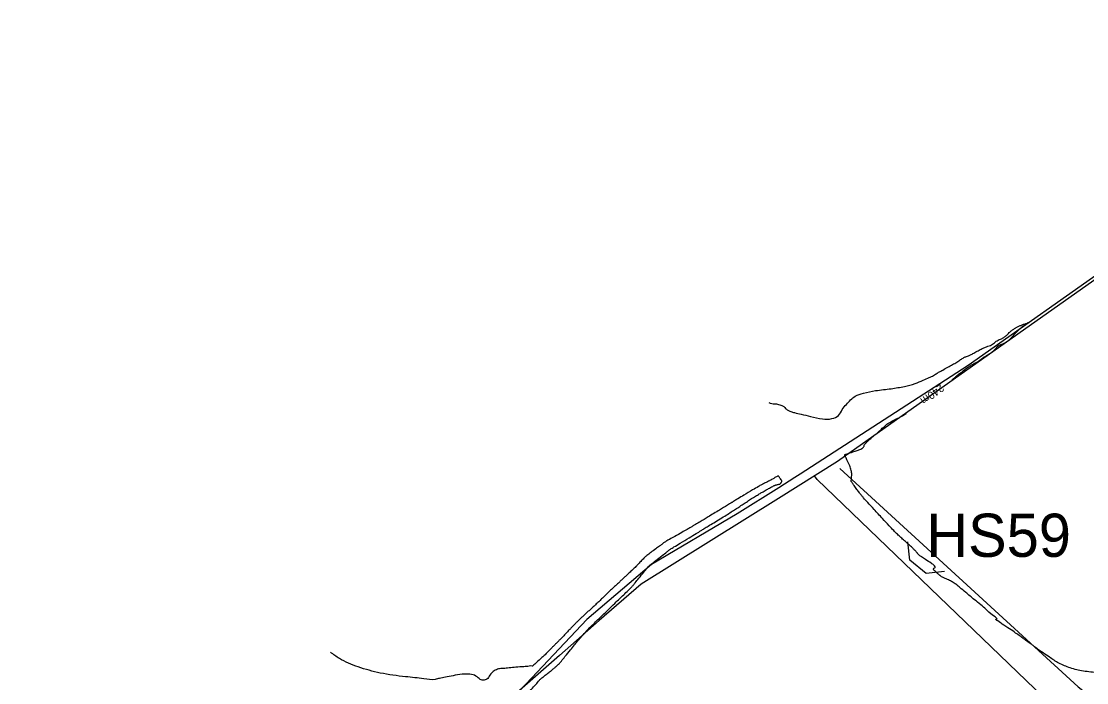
# Model space of a CAD drawing. Extents: x -478495 to -472450, y -1118050 to -1113745.
# Drawn here: x -477223 to -476976.4, y -1115068.9 to -1114915.9 of the extents above; entities that cross this region are included whole.
import ezdxf

# ---------------------------------------------------------------- set-up
doc = ezdxf.new("R2010")
doc.units = 0
for name, color, linetype in [('cyklostezka', 7, 'Continuous'), ('hospodářské sjezdy', 7, 'Continuous'), ('hranice kú', 7, 'Continuous'), ('ObPÚ', 7, 'Continuous'), ('silnice', 7, 'Continuous'), ('vodní plochy', 7, 'Continuous'), ('Vrstevnice_hlavni', 7, 'Continuous'), ('Vrstevnice_popis', 7, 'Continuous'), ('Vrstevnice_vedlejsi', 7, 'Continuous')]:
    doc.layers.add(name, color=color, linetype=linetype)

msp = doc.modelspace()

# ---------------------------------------------------------------- linework, layer by layer
at = {"layer": 'cyklostezka'}
msp.add_lwpolyline([(-477033.5754190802, -1115019.3150603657), (-476978.4562666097, -1115069.8432601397), (-476859.56050309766, -1115163.970078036), (-476838.56618741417, -1115180.4272610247), (-476823.49769734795, -1115192.2844335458), (-476742.0352354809, -1115258.9995421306), (-476654.0177406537, -1115335.224940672), (-476615.8651919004, -1115370.6739552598), (-476567.0504242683, -1115426.523456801)], dxfattribs=at)
at = {"layer": 'hospodářské sjezdy'}
for p, q in [((-477017.369, -1115040.5760000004), (-477017.839838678, -1115036.3366136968)), ((-477013.55639166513, -1115043.6302121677), (-477017.369, -1115040.5760000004)), ((-477009.31643236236, -1115043.1645616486), (-477013.55639166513, -1115043.6302121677))]:
    msp.add_line(p, q, dxfattribs=at)
at = {"layer": 'hranice kú'}
for p, q in [((-476889.77970592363, -1114915.8720498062), (-477034.1014911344, -1115017.6843978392)), ((-477034.1014911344, -1115017.6843978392), (-477047.776208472, -1115026.2470712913)), ((-477047.776208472, -1115026.2470712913), (-477079.5238625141, -1115046.1264434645)), ((-477079.5238625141, -1115046.1264434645), (-477089.23482985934, -1115054.5264088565)), ((-477089.23482985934, -1115054.5264088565), (-477098.4353740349, -1115062.5768850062)), ((-477098.4353740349, -1115062.5768850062), (-477120.9851096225, -1115082.3079036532))]:
    msp.add_line(p, q, dxfattribs=at)
at = {"layer": 'ObPÚ'}
for p, q in [((-476889.77970592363, -1114915.8720498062), (-477034.1014911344, -1115017.6843978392)), ((-477034.1014911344, -1115017.6843978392), (-477047.776208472, -1115026.2470712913)), ((-477047.776208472, -1115026.2470712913), (-477079.5238625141, -1115046.1264434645)), ((-477079.5238625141, -1115046.1264434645), (-477089.23482985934, -1115054.5264088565)), ((-477089.23482985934, -1115054.5264088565), (-477098.4353740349, -1115062.5768850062)), ((-477098.4353740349, -1115062.5768850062), (-477120.9851096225, -1115082.3079036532))]:
    msp.add_line(p, q, dxfattribs=at)
at = {"layer": 'silnice'}
msp.add_lwpolyline([(-476200.5430969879, -1116268.1533225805), (-476239.9646638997, -1116179.1988064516), (-476260.9335824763, -1116109.5457419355), (-476288.6125549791, -1116007.1641290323), (-476289.4513117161, -1115970.2396129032), (-476274.35369035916, -1115930.797516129), (-476257.5785554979, -1115904.782516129), (-476369.13277385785, -1115816.6670000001), (-476386.7466654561, -1115803.239903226), (-476421.13569191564, -1115718.4813548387), (-476492.4300150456, -1115557.3561935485), (-476531.85169606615, -1115480.150387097), (-476576.30580343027, -1115421.4068387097), (-476632.5025051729, -1115358.4673225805), (-476738.18585476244, -1115266.156032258), (-476821.72644138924, -1115198.097580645), (-476986.4582147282, -1115072.218548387), (-477038.7966192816, -1115021.8669354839), (-477039.4315830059, -1115021.0219319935)], dxfattribs=at)
at = {"layer": 'vodní plochy'}
msp.add_lwpolyline([(-476969.074, -1114970.997), (-477003.853, -1114995.482), (-477042.717, -1115020.6670000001), (-477043.996, -1115021.391), (-477047.718, -1115023.7920000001), (-477057.356, -1115029.838), (-477077.169, -1115041.531), (-477092.092, -1115054.27), (-477110.00200000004, -1115073.251), (-477118.905, -1115081.598), (-477126.545, -1115085.486), (-477135.50800000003, -1115088.514), (-477142.313, -1115089.0590000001), (-477143.75, -1115088.538), (-477177.386, -1115076.347), (-477192.107, -1115077.213), (-477204.809, -1115080.97), (-477217.213, -1115089.231), (-477222.967, -1115093.062)], dxfattribs=at)
at = {"layer": 'Vrstevnice_hlavni'}
for points in [[(-477049.97945449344, -1115004.0292969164), (-477049.673, -1115004.193), (-477048.26, -1115004.404), (-477047.204, -1115004.683), (-477046.505, -1115005.027), (-477046.164, -1115005.438), (-477045.639, -1115005.805), (-477044.929, -1115006.127), (-477044.034, -1115006.405), (-477042.50800000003, -1115006.787), (-477040.351, -1115007.273), (-477037.56200000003, -1115007.8630000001), (-477035.407, -1115007.799), (-477033.886, -1115007.079), (-477033, -1115005.704), (-477032.06200000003, -1115004.503), (-477031.07300000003, -1115003.477), (-477030.034, -1115002.625), (-477028.119, -1115001.9070000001), (-477025.32800000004, -1115001.324), (-477021.663, -1115000.876), (-477018.599, -1115000.325), (-477016.13800000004, -1114999.672), (-477014.278, -1114998.9170000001), (-477012.873, -1114998.304), (-477011.923, -1114997.835), (-477011.428, -1114997.509), (-477010.705, -1114997.08), (-477009.754, -1114996.549), (-477008.574, -1114995.914), (-477007.49100000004, -1114995.299), (-477006.505, -1114994.702), (-477005.61600000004, -1114994.125), (-477004.874, -1114993.69), (-477004.28, -1114993.398), (-477003.833, -1114993.249), (-477003.188, -1114992.955), (-477002.34500000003, -1114992.516), (-477001.305, -1114991.933), (-477000.403, -1114991.481), (-476999.64, -1114991.162), (-476999.016, -1114990.973), (-476998.46400000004, -1114990.7280000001), (-476997.985, -1114990.425), (-476997.579, -1114990.066), (-476997.143, -1114989.7650000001), (-476996.67600000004, -1114989.524), (-476996.178, -1114989.342), (-476995.62700000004, -1114989.011), (-476995.023, -1114988.533), (-476994.365, -1114987.9070000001), (-476993.74100000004, -1114987.384), (-476993.153, -1114986.963), (-476992.599, -1114986.645), (-476992.009, -1114986.355), (-476991.38300000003, -1114986.092), (-476990.719, -1114985.856), (-476990.255, -1114985.689), (-476989.99100000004, -1114985.591), (-476989.925, -1114985.561), (-476989.901, -1114985.553), (-476989.919, -1114985.568), (-476989.977, -1114985.605), (-476990.02, -1114985.633), (-476990.048, -1114985.653), (-476990.061, -1114985.663), (-476990.326, -1114985.857), (-476990.841, -1114986.233), (-476991.608, -1114986.7920000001), (-476992.308, -1114987.388), (-476992.94, -1114988.02), (-476993.504, -1114988.689), (-476994.025, -1114989.245), (-476994.503, -1114989.688), (-476994.93700000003, -1114990.017), (-476995.402, -1114990.301), (-476995.89900000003, -1114990.54), (-476996.428, -1114990.734), (-476996.92, -1114991.026), (-476997.375, -1114991.4170000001), (-476997.795, -1114991.906), (-476998.298, -1114992.365), (-476998.884, -1114992.793), (-476999.553, -1114993.19), (-477000.21400000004, -1114993.61), (-477000.867, -1114994.052), (-477001.512, -1114994.518), (-477002.106, -1114994.9070000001), (-477002.64900000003, -1114995.22), (-477003.142, -1114995.458), (-477003.814, -1114995.885), (-477004.66500000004, -1114996.502)], [(-477004.66500000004, -1114996.502), (-477005.695, -1114997.3090000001), (-477006.489, -1114997.933), (-477007.047, -1114998.372), (-477007.691, -1114998.882)], [(-477017.89400000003, -1115036.673), (-477018.831, -1115035.848), (-477019.673, -1115035.079), (-477020.422, -1115034.367), (-477021.076, -1115033.712), (-477022.168, -1115032.564), (-477023.697, -1115030.923), (-477025.662, -1115028.788), (-477027.12200000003, -1115027.188), (-477028.074, -1115026.1230000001), (-477028.52, -1115025.593), (-477029.034, -1115024.943), (-477029.617, -1115024.173), (-477030.26900000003, -1115023.2820000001), (-477030.708, -1115022.682), (-477030.934, -1115022.374), (-477030.946, -1115022.357), (-477030.928, -1115022.077), (-477030.878, -1115021.535), (-477030.797, -1115020.729), (-477030.934, -1115019.788), (-477031.286, -1115018.713), (-477031.856, -1115017.503), (-477032.238, -1115016.683), (-477032.433, -1115016.253), (-477032.44, -1115016.214), (-477032.443, -1115016.185), (-477032.441, -1115016.166), (-477032.435, -1115016.159), (-477032.431, -1115016.153), (-477032.428, -1115016.149), (-477032.42600000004, -1115016.147), (-477032.373, -1115016.122), (-477032.267, -1115016.074), (-477032.11, -1115016.003), (-477031.64, -1115015.843), (-477030.858, -1115015.5960000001), (-477029.76300000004, -1115015.26), (-477028.95900000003, -1115014.975), (-477028.444, -1115014.74), (-477028.219, -1115014.556), (-477028.06, -1115014.364), (-477027.968, -1115014.165), (-477027.943, -1115013.958), (-477027.674, -1115013.593), (-477027.161, -1115013.071), (-477026.405, -1115012.392), (-477025.889, -1115011.927), (-477025.61600000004, -1115011.677), (-477025.583, -1115011.642), (-477025.534, -1115011.602), (-477025.469, -1115011.556), (-477025.387, -1115011.5050000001), (-477025.033, -1115011.2010000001), (-477024.407, -1115010.643), (-477023.509, -1115009.833), (-477022.858, -1115009.263), (-477022.455, -1115008.935), (-477022.299, -1115008.848), (-477021.99100000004, -1115008.674), (-477021.533, -1115008.413), (-477020.923, -1115008.064), (-477020.468, -1115007.8260000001), (-477020.167, -1115007.697), (-477020.021, -1115007.678), (-477019.88300000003, -1115007.635), (-477019.754, -1115007.567), (-477019.63300000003, -1115007.475), (-477019.398, -1115007.325), (-477019.047, -1115007.117), (-477018.115, -1115006.584)], [(-476873.251, -1115143.677), (-476873.507, -1115142.01), (-476873.554, -1115139.102), (-476873.522, -1115134.12), (-476873.41000000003, -1115127.063), (-476873.808, -1115122.0860000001), (-476874.717, -1115119.19), (-476876.136, -1115118.374), (-476877.354, -1115117.171), (-476878.371, -1115115.579), (-476879.185, -1115113.6), (-476882.364, -1115111.475), (-476887.908, -1115109.205), (-476895.815, -1115106.789), (-476902.242, -1115103.761), (-476907.186, -1115100.12), (-476910.64900000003, -1115095.867), (-476913.66000000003, -1115091.883), (-476916.218, -1115088.1670000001), (-476918.324, -1115084.72), (-476919.72500000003, -1115082.379), (-476920.42100000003, -1115081.145), (-476920.412, -1115081.017), (-476920.42600000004, -1115080.932), (-476920.462, -1115080.891), (-476920.521, -1115080.893), (-476920.576, -1115080.895), (-476920.62700000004, -1115080.896), (-476920.674, -1115080.898), (-476921.73600000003, -1115080.799), (-476923.814, -1115080.599), (-476926.907, -1115080.3), (-476932.302, -1115079.591), (-476940, -1115078.472), (-476950, -1115076.9440000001), (-476957.876, -1115075.006), (-476963.629, -1115072.6570000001), (-476967.259, -1115069.897), (-476970.802, -1115067.892), (-476974.259, -1115066.643), (-476977.631, -1115066.149), (-476980.601, -1115065.341), (-476983.17, -1115064.218), (-476985.338, -1115062.781), (-476986.878, -1115061.747), (-476987.79000000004, -1115061.118), (-476988.074, -1115060.892), (-476988.478, -1115060.587), (-476989.003, -1115060.204), (-476989.648, -1115059.743), (-476990.332, -1115059.246), (-476991.055, -1115058.714), (-476991.817, -1115058.146), (-476992.891, -1115057.395), (-476994.277, -1115056.46), (-476995.976, -1115055.343), (-476997.039, -1115054.593), (-476997.46400000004, -1115054.21), (-476997.254, -1115054.195), (-476998.009, -1115053.437), (-476999.729, -1115051.937), (-477002.416, -1115049.693), (-477004.444, -1115048.001), (-477005.814, -1115046.86), (-477006.527, -1115046.27), (-477007.324, -1115045.723), (-477008.206, -1115045.2210000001), (-477009.173, -1115044.763), (-477009.833, -1115044.445), (-477010.186, -1115044.267), (-477010.232, -1115044.2280000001), (-477010.318, -1115044.158), (-477010.443, -1115044.058), (-477010.608, -1115043.927), (-477010.86600000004, -1115043.703), (-477011.219, -1115043.389), (-477011.666, -1115042.982), (-477011.859, -1115042.654), (-477011.79600000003, -1115042.405), (-477011.479, -1115042.235), (-477011.695, -1115041.8460000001), (-477012.445, -1115041.236), (-477013.729, -1115040.4070000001), (-477014.642, -1115039.799), (-477015.184, -1115039.41), (-477015.355, -1115039.241), (-477015.476, -1115039.117), (-477015.545, -1115039.038), (-477015.564, -1115039.003), (-477015.672, -1115038.875), (-477015.869, -1115038.653), (-477016.157, -1115038.339), (-477016.405, -1115038.07), (-477016.615, -1115037.849), (-477016.786, -1115037.674), (-477017.213, -1115037.2820000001), (-477017.89400000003, -1115036.673)]]:
    msp.add_spline(points, degree=3, dxfattribs=at)
at = {"layer": 'Vrstevnice_vedlejsi'}
for points in [[(-477108.02400000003, -1115073.453), (-477107.41000000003, -1115072.982), (-477106.961, -1115072.629), (-477106.67600000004, -1115072.395), (-477106.556, -1115072.278), (-477106.091, -1115071.757), (-477105.281, -1115070.832), (-477104.126, -1115069.502), (-477103.309, -1115068.574), (-477102.82800000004, -1115068.046), (-477102.685, -1115067.92), (-477102.316, -1115067.626), (-477101.72000000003, -1115067.165), (-477100.898, -1115066.537), (-477100.184, -1115065.97), (-477099.579, -1115065.464), (-477099.081, -1115065.02), (-477098.73, -1115064.7010000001), (-477098.52400000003, -1115064.509), (-477098.465, -1115064.4440000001), (-477098.01, -1115063.889), (-477097.162, -1115062.844), (-477095.919, -1115061.311), (-477094.978, -1115060.158), (-477094.33900000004, -1115059.385), (-477094.00200000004, -1115058.992), (-477093.57, -1115058.494), (-477093.044, -1115057.889), (-477092.423, -1115057.178), (-477091.967, -1115056.663), (-477091.675, -1115056.343), (-477091.547, -1115056.218), (-477091.414, -1115056.093), (-477091.276, -1115055.968), (-477091.13300000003, -1115055.843), (-477090.09, -1115054.841), (-477088.145, -1115052.963), (-477085.299, -1115050.207), (-477083.32800000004, -1115048.299), (-477082.232, -1115047.2380000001), (-477082.012, -1115047.025), (-477081.803, -1115046.81), (-477081.606, -1115046.593), (-477081.422, -1115046.376), (-477080.916, -1115045.76), (-477080.09, -1115044.745), (-477078.942, -1115043.332), (-477078.16500000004, -1115042.381), (-477077.759, -1115041.889), (-477077.722, -1115041.859), (-477077.193, -1115041.4440000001), (-477076.17100000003, -1115040.644), (-477074.656, -1115039.459), (-477073.586, -1115038.6230000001), (-477072.96, -1115038.136), (-477072.77900000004, -1115037.999), (-477071.961, -1115037.49), (-477070.50800000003, -1115036.61), (-477068.419, -1115035.359), (-477066.799, -1115034.381), (-477065.64900000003, -1115033.675), (-477064.968, -1115033.243), (-477064.004, -1115032.647), (-477062.756, -1115031.889), (-477061.226, -1115030.967), (-477059.874, -1115030.136), (-477058.7, -1115029.396), (-477057.706, -1115028.747), (-477056.705, -1115028.092), (-477055.69800000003, -1115027.432), (-477054.685, -1115026.767), (-477053.73, -1115026.1570000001), (-477052.836, -1115025.601), (-477052, -1115025.101), (-477051.326, -1115024.7), (-477050.814, -1115024.399), (-477050.463, -1115024.197), (-477050.058, -1115023.975), (-477049.60000000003, -1115023.733), (-477049.08900000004, -1115023.47), (-477048.739, -1115023.29), (-477048.55100000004, -1115023.192), (-477048.525, -1115023.177), (-477048.392, -1115023.144), (-477048.151, -1115023.091), (-477047.802, -1115023.02), (-477047.55700000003, -1115022.962), (-477047.416, -1115022.9170000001), (-477047.38, -1115022.886), (-477047.304, -1115022.801), (-477047.188, -1115022.663), (-477047.034, -1115022.472), (-477047.02400000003, -1115022.224), (-477047.159, -1115021.92), (-477047.44, -1115021.5590000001), (-477047.642, -1115021.3), (-477047.764, -1115021.143)], [(-477047.764, -1115021.143), (-477047.80700000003, -1115021.087), (-477047.84, -1115021.051), (-477047.862, -1115021.035), (-477047.874, -1115021.038), (-477048.066, -1115021.148), (-477048.439, -1115021.365), (-477048.993, -1115021.689), (-477049.369, -1115021.906), (-477049.566, -1115022.018), (-477049.585, -1115022.024), (-477049.603, -1115022.0320000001), (-477049.62, -1115022.044), (-477049.636, -1115022.0590000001), (-477049.869, -1115022.179), (-477050.319, -1115022.405), (-477050.98600000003, -1115022.735), (-477051.44, -1115022.9610000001), (-477051.68, -1115023.08), (-477051.707, -1115023.094), (-477052.39400000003, -1115023.504), (-477053.742, -1115024.308), (-477055.751, -1115025.507), (-477057.143, -1115026.339), (-477057.916, -1115026.803), (-477058.072, -1115026.899), (-477058.233, -1115027.001), (-477058.398, -1115027.108), (-477058.569, -1115027.2210000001), (-477059.569, -1115027.831), (-477061.39900000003, -1115028.936), (-477064.059, -1115030.537), (-477065.922, -1115031.6570000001), (-477066.987, -1115032.295), (-477067.255, -1115032.4510000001), (-477067.533, -1115032.618), (-477067.822, -1115032.796), (-477068.12200000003, -1115032.984), (-477068.88, -1115033.421), (-477070.096, -1115034.105), (-477071.77, -1115035.038), (-477072.989, -1115035.726), (-477073.751, -1115036.168), (-477074.05700000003, -1115036.365), (-477074.333, -1115036.554), (-477074.579, -1115036.736), (-477074.794, -1115036.91), (-477075.324, -1115037.31), (-477076.168, -1115037.936), (-477077.327, -1115038.79), (-477078.20300000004, -1115039.464), (-477078.798, -1115039.959), (-477079.11100000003, -1115040.275), (-477079.455, -1115040.634), (-477079.831, -1115041.038), (-477080.238, -1115041.485), (-477080.787, -1115042.043), (-477081.476, -1115042.712), (-477082.30700000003, -1115043.493), (-477083.01900000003, -1115044.159), (-477083.61, -1115044.71), (-477084.082, -1115045.147), (-477084.651, -1115045.674), (-477085.315, -1115046.29), (-477086.075, -1115046.995), (-477086.782, -1115047.662), (-477087.43700000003, -1115048.2920000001), (-477088.038, -1115048.885), (-477088.68200000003, -1115049.509), (-477089.369, -1115050.164), (-477090.097, -1115050.851), (-477090.791, -1115051.495), (-477091.451, -1115052.094), (-477092.076, -1115052.649), (-477092.683, -1115053.204), (-477093.273, -1115053.758), (-477093.846, -1115054.312), (-477094.405, -1115054.864), (-477094.949, -1115055.416), (-477095.479, -1115055.966), (-477096.07300000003, -1115056.582), (-477096.731, -1115057.264), (-477097.45300000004, -1115058.011), (-477098.08400000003, -1115058.661), (-477098.62700000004, -1115059.215), (-477099.079, -1115059.673), (-477099.591, -1115060.191), (-477100.163, -1115060.77), (-477100.794, -1115061.411), (-477101.243, -1115061.866), (-477101.509, -1115062.137), (-477101.593, -1115062.222), (-477101.981, -1115062.587), (-477102.673, -1115063.234), (-477103.67, -1115064.162), (-477104.352, -1115064.774), (-477104.719, -1115065.07)], [(-477104.719, -1115065.07), (-477104.772, -1115065.05), (-477105.42100000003, -1115065.088), (-477106.667, -1115065.183), (-477108.511, -1115065.3360000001), (-477110.106, -1115065.477), (-477111.454, -1115065.605), (-477112.553, -1115065.7210000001), (-477113.51900000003, -1115066.142), (-477114.351, -1115066.867), (-477115.049, -1115067.896), (-477115.853, -1115068.3190000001), (-477116.761, -1115068.135), (-477117.775, -1115067.344), (-477119.166, -1115066.938), (-477120.933, -1115066.918), (-477123.077, -1115067.283), (-477124.83400000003, -1115067.608), (-477126.206, -1115067.891), (-477127.191, -1115068.133), (-477129.805, -1115068.007), (-477134.047, -1115067.513), (-477139.917, -1115066.65), (-477145.027, -1115065.24), (-477149.376, -1115063.284), (-477151.42003076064, -1115061.8544727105)]]:
    msp.add_spline(points, degree=3, dxfattribs=at)

# ---------------------------------------------------------------- texts
at = {"layer": 'hospodářské sjezdy'}
msp.add_text('HS59', height=9.999999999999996, rotation=359.99999385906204, dxfattribs=at).set_placement((-477013.54410765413, -1115039.7797199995))
at = {"layer": 'Vrstevnice_popis'}
msp.add_text(' 240m ', height=1.8000000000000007, rotation=216.46087583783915, dxfattribs=at).set_placement((-477009.746, -1114999.2820000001))

doc.saveas('drawing.dxf')
